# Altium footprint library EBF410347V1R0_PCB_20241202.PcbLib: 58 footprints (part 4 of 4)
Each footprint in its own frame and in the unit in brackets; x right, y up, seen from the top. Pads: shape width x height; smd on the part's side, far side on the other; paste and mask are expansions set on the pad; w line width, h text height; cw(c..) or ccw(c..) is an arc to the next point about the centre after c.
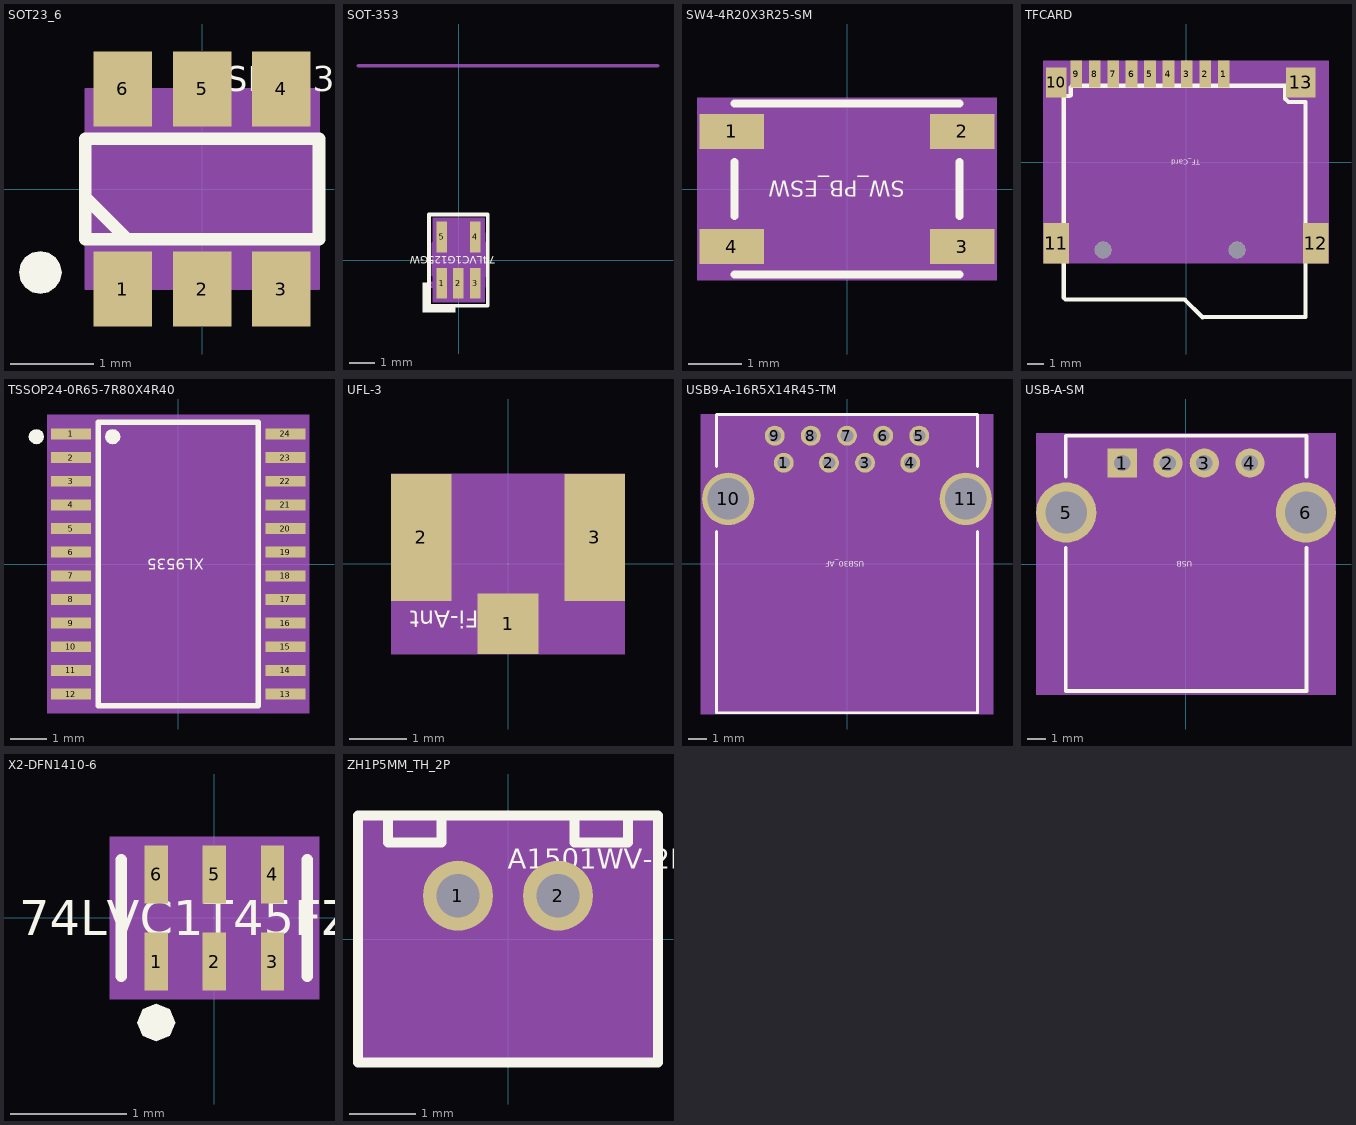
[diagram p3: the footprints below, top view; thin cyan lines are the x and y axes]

## SOT23_6 [mm] "SOT23_6"
pads (6):
  rect 0.7x0.9 smd: 1(-0.95,-1.2) 2(0,-1.2) 3(0.95,-1.2) 4(0.95,1.2) 5(0,1.2) 6(-0.95,1.2)
Top Overlay:
  dashed: -1.94,-1.255 -1.842,-1.235 -1.76,-1.18 -1.705,-1.098 -1.685,-1 -1.705,-0.902 -1.723,-0.875 -1.76,-0.82 -1.842,-0.765 -1.94,-0.745 -2.038,-0.765 -2.12,-0.82 -2.157,-0.875 -2.175,-0.902 -2.195,-1 -2.175,-1.098 -2.12,-1.18 -2.038,-1.235
  lines w0.15: -1.4,-0.1 -0.9,-0.6 ; -1.4,-0.6 -1.4,0.6 1.4,0.6 1.4,-0.6 -1.4,-0.6
  text "ASP9135ZC-R" at 0,1.17 h0.3
Top 3D Body:
  region: -1.4,-1.2 1.4,-1.2 1.4,1.2 -1.4,1.2
Mechanical 14:
  text "1" at -0.95,-0.946 h0.64
  text "4" at 0.95,1.454 h0.64
  text "6" at -0.95,1.454 h0.64
  text "2" at 0,-0.946 h0.64
  text "3" at 0.95,-0.946 h0.64
  text "5" at 0,1.454 h0.64
Top Assembly:
  lines w0.025: -1.4,-1.2 1.4,-1.2 1.4,1.2 -1.4,1.2 -1.4,-1.2
3D body: height 3.81, standoff 0, extent -1.4,-1.2 1.4,1.2

## SOT-353 [mil] "SOT-353"
pads (5):
  rect 16x47 smd: 1(-25.91,-35.43) 2(-0.32,-35.43) 3(25.28,-35.43) 4(25.28,35.43) 5(-25.91,35.43)
Top Overlay:
  dashed: -45.31,-35 -55.31,-35 -55.31,-80 -5.32,-80 -5.32,-70 -45.31,-70
  lines w6: -45.31,-70 44.69,-70 44.69,70 -45.31,70 -45.31,-70
  text "74LVC1G125GW" at 56.69,5.91 h11.81
  text ".Designator" at 14.17,5.91 h11.81
Mechanical 5:
  dashed: -39.69,-65 39.69,-65 39.69,65 -39.69,65
Top 3D Body:
  region: -39.69,-65 39.69,-65 39.69,65 -39.69,65
Top Component Center:
  circle w1: c-0.32,0 r11.81
  circle w1: c-0.32,0 r11.81
  lines w1: -16.06,0 15.43,0 -16.06,0 ; -0.32,-15.75 -0.32,15.75 -0.32,-15.75
Mechanical 14:
  text "4" at 31.28,35.43 h15
  text "1" at -19.91,-35.43 h15
  text "3" at 31.28,-35.43 h15
  text "2" at 5.68,-35.43 h15
  text "5" at -19.91,35.43 h15
Top Assembly:
  circle w3.94: c-41.31,-38 r2.83
  lines w3.94: -32.31,-24 -32.31,-40.83 -20.32,-40.83 ; -31.5,26 -31.5,40.83 ; -31.5,41.83 -19.5,41.83 -19.5,26 ; -20.32,-40 -20.32,-25 ; -6.32,-24 -6.32,-40.83 5.68,-40.83 ; 5.68,-40 5.68,-24 ; 19.68,-24 19.68,-40.83 31.68,-40.83 ; 19.68,26 19.68,41 ; 19.68,41.83 31.68,41.83 31.68,26 ; 31.68,-40 31.68,-24 ; -39.31,-23.61 40.69,-23.61 40.69,25.61 -39.31,25.61 -39.31,-23.61
Mechanical 18:
  lines w5: -154.31,298 305.69,298
  text "Remark: ***" at -124.31,98 h25
  text "Rev   : A1" at -124.31,138 h25
  text "Date  : 2007-11-30" at -124.31,178 h25
  text "Creat : Yuki" at -124.31,218 h25
  text "Ref PN: ESDALC6V1W5" at -124.31,258 h25
  text "Sofer Lib Information" at -154.31,308 h25
Mechanical 20:
  lines w1: -39.31,-41 40.69,-41 40.69,42 -39.31,42 -39.31,-41
Mechanical 21:
  text "Approved" at 47.69,0 h15
Mechanical 22:
  text "SOT-353" at 144.69,-163 h50
3D body: height 150, standoff 0, extent -39.69,-65 39.69,65

## SW4-4R20X3R25-SM [mm] "SW4-4R20X3R25-SM"
pads (4):
  rect 1.2x0.65 smd: 1(-2.15,1.075) 2(2.15,1.075) 3(2.15,-1.075) 4(-2.15,-1.075)
Top Overlay:
  lines w0.15: -2.1,-1.6 2.1,-1.6 ; -2.1,-0.5 -2.1,0.5 ; -2.1,1.6 2.1,1.6 ; 2.1,-0.5 2.1,0.5
  text "SW_PB_ESW" at 1.08,0.15 h0.3
Top 3D Body:
  region: -2.8,1.7 -2.8,-1.7 2.8,-1.7 2.8,1.7
Mechanical 14:
  text "1" at -1.592,1 h0.64
  text "2" at 2.608,0.9 h0.64
  text "3" at 2.608,-1.2 h0.64
  text "4" at -1.592,-1.2 h0.64
Top Assembly:
  lines w0.15: -2.1,-1.625 2.1,-1.625 2.1,1.625 -2.1,1.625 -2.1,-1.625
3D body: height 3.81, standoff 0, extent -2.8,-1.7 2.8,1.7

## TFCARD [mm] "TFCARD"
pads (15):
  rect 0.7x1.6 smd: 1(2.25,5.253) 2(1.15,5.253) 3(0.05,5.253) 4(-1.05,5.253) 5(-2.15,5.253) 6(-3.25,5.253) 7(-4.35,5.253) 8(-5.45,5.253) 9(-6.55,5.253)
  rect 1.2x1.778 smd: 10(-7.75,4.753)
  rect 1.524x2.413 smd: 11(-7.75,-4.847) 12(7.75,-4.847)
  rect 1.778x1.778 smd: 13(6.85,4.753)
  round 1 hole 1 unplated: ""(-4.95,-5.247) ""(3.05,-5.247)
Top Overlay:
  lines w0.254: -7.344,3.942 -7.293,3.891 -7.293,-8.098 -7.191,-8.2 -0.079,-8.2 0.988,-9.266 7.134,-9.247 7.134,3.586 6.118,3.586 5.915,3.789 5.915,4.551 -6.785,4.551 -6.886,4.45 -6.886,3.992 -6.937,3.942 -7.344,3.942
  text "TF_Card" at 0.84,0.15 h0.3
Top 3D Body:
  region: -8.512,-6.053 8.512,-6.053 8.512,6.053 -8.512,6.053
Mechanical 14:
  text "6" at -3.047,5.253 h0.51
  text "12" at 8.156,-4.847 h0.51
  text "10" at -7.344,4.753 h0.51
  text "11" at -7.344,-4.847 h0.51
  text "13" at 7.256,4.753 h0.51
  text "4" at -0.847,5.253 h0.51
  text "5" at -1.947,5.253 h0.51
  text "1" at 2.453,5.253 h0.51
  text "9" at -6.347,5.253 h0.51
  text "8" at -5.247,5.253 h0.51
  text "7" at -4.147,5.253 h0.51
  text "3" at 0.253,5.253 h0.51
  text "2" at 1.353,5.253 h0.51
3D body: height 3.81, standoff 0, extent -8.512,-6.053 8.512,6.053

## TSSOP24-0R65-7R80X4R40 [mm] "TSSOP24-0R65-7R80X4R40"
pads (24):
  rect 1.1x0.3 smd: 1(-2.95,3.575) 2(-2.95,2.925) 3(-2.95,2.275) 4(-2.95,1.625) 5(-2.95,0.975) 6(-2.95,0.325) 7(-2.95,-0.325) 8(-2.95,-0.975) 9(-2.95,-1.625) 10(-2.95,-2.275) 11(-2.95,-2.925) 12(-2.95,-3.575) 13(2.95,-3.575) 14(2.95,-2.925) 15(2.95,-2.275) 16(2.95,-1.625) 17(2.95,-0.975) 18(2.95,-0.325) 19(2.95,0.325) 20(2.95,0.975) 21(2.95,1.625) 22(2.95,2.275) 23(2.95,2.925) 24(2.95,3.575)
Top Overlay:
  dashed: -4.104,3.5 -4.088,3.422 -4.044,3.356 -3.978,3.312 -3.9,3.296 -3.822,3.312 -3.8,3.326 -3.756,3.356 -3.712,3.422 -3.696,3.5 -3.712,3.578 -3.756,3.644 -3.8,3.674 -3.822,3.688 -3.9,3.704 -3.978,3.688 -4.044,3.644 -4.088,3.578
  dashed: -2.004,3.5 -1.988,3.422 -1.944,3.356 -1.878,3.312 -1.8,3.296 -1.722,3.312 -1.7,3.326 -1.656,3.356 -1.612,3.422 -1.596,3.5 -1.612,3.578 -1.656,3.644 -1.7,3.674 -1.722,3.688 -1.8,3.704 -1.878,3.688 -1.944,3.644 -1.988,3.578
  lines w0.15: -2.2,-3.9 -2.2,3.9 2.2,3.9 2.2,-3.9 -2.2,-3.9
  text "XL9535" at 0.72,0.15 h0.3
Top 3D Body:
  region: -3.6,4.1 -3.6,-4.1 3.6,-4.1 3.6,4.1
Mechanical 14:
  text "21" at 3.15,1.525 h0.25
  text "14" at 3.15,-3.025 h0.25
  text "15" at 3.15,-2.375 h0.25
  text "16" at 3.15,-1.725 h0.25
  text "17" at 3.15,-1.075 h0.25
  text "18" at 3.15,-0.425 h0.25
  text "19" at 3.15,0.225 h0.25
  text "20" at 3.15,0.875 h0.25
  text "1" at -2.85,3.475 h0.25
  text "9" at -2.85,-1.725 h0.25
  text "8" at -2.85,-1.075 h0.25
  text "7" at -2.85,-0.425 h0.25
  text "6" at -2.85,0.225 h0.25
  text "13" at 3.15,-3.675 h0.25
  text "12" at -2.75,-3.675 h0.25
  text "3" at -2.85,2.175 h0.25
  text "2" at -2.85,2.825 h0.25
  text "22" at 3.15,2.175 h0.25
  text "23" at 3.15,2.825 h0.25
  text "24" at 3.15,3.475 h0.25
  text "11" at -2.75,-3.025 h0.25
  text "10" at -2.75,-2.375 h0.25
  text "4" at -2.85,1.525 h0.25
  text "5" at -2.85,0.875 h0.25
Top Assembly:
  lines w0.15: -3.2,-3.9 -3.2,3.9 3.2,3.9 3.2,-3.9 -3.2,-3.9
3D body: height 3.81, standoff 0, extent -3.6,-4.1 3.6,4.1

## UFL-3 [mm] "UFL-3"
pads (3):
  rect 1.05x1.05 smd: 1(0,-1.038)
  rect 1.05x2.2 smd: 2(-1.5,0.462) 3(1.5,0.462)
Top Overlay:
  text "WiFi-Ant" at 0,-0.81 h0.3
Top 3D Body:
  region: -2.025,-1.563 2.025,-1.563 2.025,1.563 -2.025,1.563
Mechanical 14:
  text "2" at -1.5,0.259 h0.51
  text "3" at 1.5,0.259 h0.51
  text "1" at 0,-1.241 h0.51
3D body: height 3.81, standoff 0, extent -2.025,-1.563 2.025,1.563

## USB9-A-16R5X14R45-TM [mm] "USB9-A-16R5X14R45-TM"
pads (11):
  round 1.1 hole 0.7: 1(-3.5,5.6) 2(-1,5.6) 3(1,5.6) 4(3.5,5.6) 5(4,7.1) 6(2,7.1) 7(0,7.1) 8(-2,7.1) 9(-4,7.1)
  round 2.9 hole 2.3: 10(-6.57,3.6) 11(6.57,3.6)
Top Overlay:
  lines w0.15: -7.225,1.8 -7.225,-8.23 7.225,-8.23 7.225,1.8 ; -7.225,5.4 -7.225,8.27 7.225,8.27 7.225,5.4
  text "USB30_AF" at 0.96,0.15 h0.3
Bottom Overlay:
  circle w0.3: c-4,7.1 r0.8
  circle w0.3: c-3.5,5.6 r0.8
  circle w0.3: c3.5,5.6 r0.8
  circle w0.3: c4,7.1 r0.8
  circle w0.5: c-2,7.1 r0.9
  circle w0.5: c-1,5.6 r0.9
  circle w0.5: c0,7.1 r0.9
  circle w0.5: c1,5.6 r0.9
  circle w0.5: c2,7.1 r0.9
Top 3D Body:
  region: -8.1,8.3 -8.1,-8.3 8.1,-8.3 8.1,8.3
Mechanical 14:
  text "4" at 3.754,5.6 h0.64
  text "7" at 0.254,7.1 h0.64
  text "6" at 2.254,7.1 h0.64
  text "9" at -3.746,7.1 h0.64
  text "2" at -0.746,5.6 h0.64
  text "8" at -1.746,7.1 h0.64
  text "3" at 1.254,5.6 h0.64
  text "11" at 7.078,3.6 h0.64
  text "10" at -6.062,3.6 h0.64
  text "5" at 4.254,7.1 h0.64
  text "1" at -3.246,5.6 h0.64
3D body: height 3.81, standoff 0, extent -8.1,-8.3 8.1,8.3

## USB-A-SM [mm] "USB-A-SM"
pads (6):
  rect 1.6x1.6 / inner round 1.6 / far side rect 1.6x1.6 hole 0.9: 1(-3.487,5.537)
  round 1.6 hole 0.9: 2(-0.987,5.537) 3(1.013,5.537) 4(3.513,5.537)
  round 3.3 hole 2.3: 5(-6.557,2.823) 6(6.583,2.823)
Top Overlay:
  lines w0.2: -6.587,0.886 -6.587,-6.963 6.613,-6.963 6.613,0.886 ; -6.587,4.781 -6.587,7.037 6.613,7.037 6.613,4.781
  text "USB" at 0.36,0.15 h0.3
Bottom Overlay:
  lines w0.2: 0.013,4.237 0.013,6.837
  lines w0.7: -2.187,4.237 -2.187,6.937 ; 2.313,4.237 2.313,6.937
  lines w0.8: -4.787,4.137 -4.787,6.937 4.813,6.937 4.813,4.137 -4.587,4.137 -4.787,4.137
Top 3D Body:
  region: -8.217,-7.163 8.217,-7.163 8.217,7.163 -8.217,7.163
Mechanical 14:
  text "4" at 3.767,5.537 h0.64
  text "2" at -0.733,5.537 h0.64
  text "3" at 1.267,5.537 h0.64
  text "1" at -3.233,5.537 h0.64
  text "6" at 6.837,2.823 h0.64
  text "5" at -6.303,2.823 h0.64
3D body: height 3.81, standoff 0, extent -8.217,-7.163 8.217,7.163

## X2-DFN1410-6 [mm] "X2-DFN1410-6"
pads (6):
  rect 0.2x0.5 smd: 1(-0.5,-0.375) 2(0,-0.375) 3(0.5,-0.375) 4(0.5,0.375) 5(0,0.375) 6(-0.5,0.375)
Top Overlay:
  dashed: -0.338,-0.9 -0.385,-0.785 -0.5,-0.738 -0.576,-0.769 -0.615,-0.785 -0.662,-0.9 -0.615,-1.015 -0.576,-1.031 -0.5,-1.062 -0.385,-1.015
  lines w0.1: -0.8,-0.5 -0.8,0.5 ; 0.8,-0.5 0.8,0.5
  text "74LVC1T45FZ4-7" at -1.68,-0.15 h0.3
Top 3D Body:
  region: -0.9,0.7 -0.9,-0.7 0.9,-0.7 0.9,0.7
Mechanical 14:
  text "4" at 0.192,0.3 h0.64
  text "2" at -0.508,-0.375 h0.64
  text "6" at -0.7,0.1 h0.64
  text "3" at 0.392,-0.4 h0.64
  text "1" at -1.008,-0.375 h0.64
  text "5" at -0.308,0.3 h0.64
Top Assembly:
  lines w0.1: -0.7,-0.5 0.7,-0.5 0.7,0.5 -0.7,0.5 -0.7,-0.5
3D body: height 3.81, standoff 0, extent -0.9,-0.7 0.9,0.7

## ZH1P5MM_TH_2P [mm] "ZH1P5MM_TH_2P"
pads (2):
  round 1.05 hole 0.65: 1(-0.75,0.65) 2(0.75,0.65)
Top Overlay:
  lines w0.15: -1.8,1.85 -1.8,1.45 -1,1.45 -1,1.85 ; 1,1.85 1,1.45 1.8,1.45 1.8,1.85 ; -2.25,-1.85 2.25,-1.85 2.25,1.85 -2.25,1.85 -2.25,-1.85
  text "A1501WV-2P" at 0,1.05 h0.3
Bottom Overlay:
  lines w0.3: 0,-0.15 0,1.45 ; -1.5,-0.15 -1.5,1.45 1.5,1.45 1.5,-0.15 -1.3,-0.15 -1.5,-0.15
Top 3D Body:
  region: -2.2,-1.85 2.2,-1.85 2.2,1.85 -2.2,1.85
Mechanical 14:
  text "2" at 0.75,1.026 h0.94
  text "1" at -0.75,1.026 h0.94
3D body: height 3.81, standoff 0, extent -2.2,-1.85 2.2,1.85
